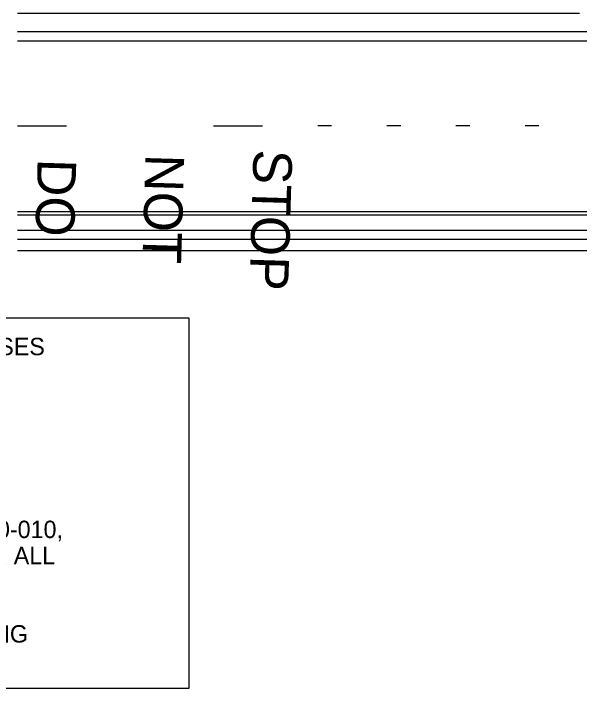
# Model space of a CAD drawing. Extents: x 524708 to 525490, y 1531861 to 1532506.
# Drawn here: x 524888.4 to 525011.2, y 1531915.8 to 1532062.3 of the extents above; entities that cross this region are included whole.
import ezdxf

# ---------------------------------------------------------------- set-up
doc = ezdxf.new("R2010")
doc.units = 0
for name, color, linetype in [('Guardrail', 7, 'Continuous'), ('PavtMessage', 7, 'Continuous'), ('PMMisc', 7, 'Continuous'), ('PMStripe6W(10-30)', 7, 'Continuous'), ('RoadwayMisc', 7, 'Continuous'), ('TextAlert', 7, 'Continuous')]:
    doc.layers.add(name, color=color, linetype=linetype)

msp = doc.modelspace()

# ---------------------------------------------------------------- linework, layer by layer
at = {"layer": 'Guardrail'}
msp.add_line((524889.23, 1532013.32), (525108.71, 1532013.32), dxfattribs=at)
at = {"layer": 'PMMisc'}
for p, q in [((524957.4, 1532037.91), (524954.4, 1532037.91)), ((524972.4, 1532037.91), (524969.4, 1532037.91)), ((524987.4, 1532037.91), (524984.39, 1532037.91)), ((525002.4, 1532037.91), (524999.4, 1532037.91))]:
    msp.add_line(p, q, dxfattribs=at)
at = {"layer": 'PMStripe6W(10-30)'}
for p, q in [((524889.23, 1532037.92), (524899.86, 1532037.92)), ((524931.76, 1532037.91), (524942.39, 1532037.91))]:
    msp.add_line(p, q, dxfattribs=at)
at = {"layer": 'RoadwayMisc'}
for p, q in [((525011.19, 1532062.32), (524889.23, 1532062.32)), ((525108.71, 1532058.32), (524889.23, 1532058.32)), ((525108.7, 1532056.32), (524889.23, 1532056.32)), ((524889.23, 1532019.32), (525108.71, 1532019.32)), ((524889.23, 1532018.65), (525108.71, 1532018.65)), ((524924.78, 1532019.32), (525108.71, 1532019.32)), ((524889.23, 1532015.32), (525108.71, 1532015.32)), ((525108.71, 1532010.82), (524889.23, 1532010.82))]:
    msp.add_line(p, q, dxfattribs=at)
at = {"layer": 'TextAlert'}
msp.add_lwpolyline([(524745.11, 1531996.25), (524926.39, 1531996.25), (524926.39, 1531915.81), (524745.11, 1531915.81)], close=True, dxfattribs=at)

# ---------------------------------------------------------------- texts
at = {"layer": 'PavtMessage'}
for s, rotation, p in [('STOP', 268.2864, (524940.47, 1532032.87)), ('NOT', 268.2864, (524917.03, 1532031.87)), ('DO', 268.2866, (524893.6, 1532030.86))]:
    msp.add_text(s, height=8.4, rotation=rotation, dxfattribs=at).set_placement(p)
at = {"layer": 'TextAlert'}
for s, p in [('1.  PLAZAS SHOWN ARE FOR INFORMATIONAL PURPOSES  ', (524751.63, 1531988.15)), ('3.  IN ACCORDANCE WITH FDOT STANDARD PLANS 700-010,', (524751.63, 1531948.46)), ('    THE USE OF NYLON WASHERS IS REQUIRED UNDER ALL', (524751.63, 1531942.79)), ('3.  DELETE THIS BOX WITH NOTES PRIOR TO INCLUDING', (524751.63, 1531925.78))]:
    msp.add_text(s, height=3.78, dxfattribs=at).set_placement(p)

doc.saveas('drawing.dxf')
